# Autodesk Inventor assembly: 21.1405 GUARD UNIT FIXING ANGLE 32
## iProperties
Created: 2007-01
Part Number: 21.1405 GUARD UNIT FIXING ANGLE 32
Document SubType Name: Assembly
Designer: Andy Moles
Author: Andy Moles
